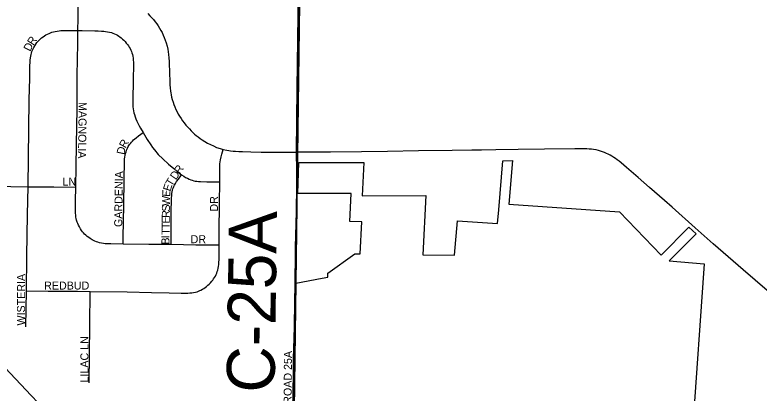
# Model space of a CAD drawing. Extents: x 0 to 680, y 0 to 440.
# Drawn here: x 483.77 to 499.3, y 268.76 to 276.66 of the extents above; entities that cross this region are included whole.
import ezdxf

# ---------------------------------------------------------------- set-up
doc = ezdxf.new("R2010")
doc.units = 0
for name, color, linetype in [('GM_X_City_Street', 7, 'Continuous'), ('GM_X_City_Street_Text', 7, 'Continuous'), ('GM_X_Corporation', 7, 'Continuous'), ('GM_X_County_Road', 7, 'Continuous'), ('GM_X_County_Road_Text', 7, 'Continuous'), ('GM_X_Interstate_Route', 7, 'Continuous'), ('GM_X_Section', 7, 'Continuous'), ('GM_X_Township_Subdivision', 7, 'Continuous'), ('GM_X_Township_Subdivision_Text', 7, 'Continuous')]:
    doc.layers.add(name, color=color, linetype=linetype)

msp = doc.modelspace()

# ---------------------------------------------------------------- linework, layer by layer
at = {"layer": 'GM_X_City_Street'}
msp.add_lwpolyline([(489.564, 267.937), (489.565, 267.993), (489.579, 268.809)], dxfattribs=at)
at = {"layer": 'GM_X_Corporation'}
msp.add_lwpolyline([(489.578, 268.503), (489.586, 269.459), (489.592, 269.713), (489.605, 270.077), (489.623, 270.72), (489.632, 271.054), (490.181, 271.16), (490.303, 271.181), (490.301, 271.265), (490.865, 271.669), (490.974, 271.667), (491.006, 272.34), (490.756, 272.347), (490.784, 272.931), (489.673, 272.926), (489.693, 273.575), (491.05, 273.58), (491.017, 272.88), (492.342, 272.885), (492.282, 271.649), (492.941, 271.638), (493.004, 272.359), (493.836, 272.304), (493.863, 272.585), (493.953, 273.614), (494.153, 273.616), (494.075, 272.707), (496.382, 272.544), (497.252, 271.643), (497.832, 272.227), (497.983, 272.09), (497.417, 271.525), (498.148, 271.46), (497.906, 267.992)], dxfattribs=at)
at = {"layer": 'GM_X_County_Road'}
for points in [[(489.648, 273.79), (489.648, 273.79), (489.658, 275.12), (489.681, 276.651), (489.681, 276.958)], [(486.546, 276.686), (486.588, 276.643), (486.629, 276.6), (486.663, 276.561), (486.698, 276.517), (486.732, 276.471), (486.76, 276.428), (486.789, 276.385), (486.816, 276.336), (486.841, 276.29), (486.866, 276.239), (486.889, 276.186), (486.908, 276.134), (486.929, 276.074), (486.946, 276.005), (486.961, 275.942), (486.969, 275.89), (486.977, 275.835), (486.985, 275.763), (486.99, 275.683), (486.999, 275.42), (487.002, 275.299), (487.007, 275.201), (487.013, 275.133), (487.019, 275.069), (487.025, 275.03), (487.031, 274.992), (487.041, 274.944), (487.053, 274.895), (487.07, 274.838), (487.087, 274.789), (487.108, 274.736), (487.13, 274.687), (487.156, 274.635), (487.181, 274.589), (487.208, 274.542), (487.239, 274.495), (487.271, 274.448), (487.303, 274.404), (487.34, 274.359), (487.374, 274.319), (487.411, 274.277), (487.447, 274.238), (487.482, 274.205), (487.52, 274.171), (487.556, 274.138), (487.592, 274.111), (487.636, 274.079), (487.68, 274.05), (487.733, 274.015), (487.791, 273.983), (487.851, 273.95), (487.912, 273.922), (487.979, 273.893), (488.054, 273.867), (488.118, 273.85)], [(488.118, 273.85), (488.19, 273.834), (488.232, 273.827), (488.272, 273.822), (488.324, 273.815), (488.376, 273.811), (488.444, 273.808), (488.519, 273.805), (488.694, 273.8), (488.909, 273.795), (489.163, 273.793), (489.648, 273.79)], [(497.323, 272.781), (497.009, 273.055), (496.771, 273.263), (496.528, 273.475), (496.415, 273.569), (496.375, 273.602), (496.336, 273.633), (496.3, 273.659), (496.262, 273.683), (496.226, 273.707), (496.188, 273.729), (496.149, 273.749), (496.111, 273.768), (496.073, 273.785), (496.032, 273.801), (495.99, 273.814), (495.945, 273.827), (495.897, 273.839), (495.844, 273.847), (495.802, 273.853), (495.752, 273.857), (495.699, 273.86), (495.639, 273.861), (495.453, 273.861), (494.819, 273.852), (494.27, 273.845), (493.801, 273.84), (493.505, 273.837)], [(491.004, 273.802), (490.354, 273.79), (489.648, 273.79)], [(489.651, 273.104), (489.651, 273.412), (489.648, 273.79)], [(493.303, 273.834), (492.892, 273.828), (492.192, 273.818), (491.546, 273.81), (491.004, 273.802)], [(493.505, 273.837), (493.303, 273.834)], [(489.616, 270.929), (489.616, 270.929), (489.627, 271.809), (489.643, 272.545), (489.651, 273.104)], [(497.48, 272.642), (497.323, 272.781)], [(499.544, 270.829), (499.46, 270.903), (498.964, 271.333), (498.337, 271.88), (497.959, 272.213), (497.48, 272.642)], [(489.609, 270.592), (489.609, 270.592), (489.613, 270.758), (489.616, 270.929)], [(489.599, 269.843), (489.604, 270.218), (489.609, 270.592)], [(489.579, 268.809), (489.589, 269.211), (489.599, 269.843)]]:
    msp.add_lwpolyline(points, dxfattribs=at)
at = {"layer": 'GM_X_Interstate_Route'}
msp.add_lwpolyline([(484.405, 268.404), (484.113, 268.711), (483.232, 269.636), (482.213, 270.707), (481.522, 271.432)], dxfattribs=at)
at = {"layer": 'GM_X_Section'}
msp.add_lwpolyline([(489.711, 276.904), (489.476, 259.394), (472.369, 259.414), (471.708, 259.407), (471.85, 277.333)], close=True, dxfattribs=at)
msp.add_lwpolyline([(507.727, 259.473), (489.476, 259.394), (489.711, 276.904)], dxfattribs=at)
at = {"layer": 'GM_X_Township_Subdivision'}
for points in [[(485.087, 276.331), (485.09, 276.584), (485.097, 277.092)], [(484.049, 273.072), (484.064, 274.277), (484.073, 274.888), (484.082, 275.34), (484.087, 275.601), (484.09, 275.666), (484.091, 275.713), (484.096, 275.762), (484.102, 275.797), (484.108, 275.829), (484.116, 275.861), (484.126, 275.894), (484.138, 275.923), (484.151, 275.954), (484.167, 275.982), (484.186, 276.015), (484.208, 276.047), (484.233, 276.081), (484.263, 276.115), (484.292, 276.145), (484.328, 276.178), (484.361, 276.202), (484.391, 276.223), (484.42, 276.241), (484.452, 276.258), (484.484, 276.274), (484.513, 276.286), (484.543, 276.297), (484.576, 276.307), (484.614, 276.316), (484.655, 276.322), (484.695, 276.327), (484.733, 276.331), (484.771, 276.332), (485.087, 276.331)], [(485.042, 273.063), (485.049, 273.495), (485.056, 273.943), (485.069, 274.702), (485.074, 275.391), (485.083, 276.064), (485.087, 276.331)], [(485.087, 276.331), (485.176, 276.331), (485.437, 276.326), (485.512, 276.324), (485.581, 276.322), (485.626, 276.319), (485.665, 276.315), (485.705, 276.309), (485.745, 276.3), (485.784, 276.289), (485.817, 276.277), (485.852, 276.263), (485.882, 276.249), (485.91, 276.235), (485.937, 276.218), (485.963, 276.2), (485.987, 276.18), (486.015, 276.156), (486.044, 276.129), (486.071, 276.101), (486.096, 276.072), (486.12, 276.043), (486.142, 276.011), (486.158, 275.985), (486.176, 275.955), (486.19, 275.925), (486.203, 275.895), (486.214, 275.865), (486.224, 275.831), (486.231, 275.796), (486.237, 275.757), (486.242, 275.714), (486.244, 275.67), (486.246, 275.626), (486.246, 275.575), (486.242, 275.353), (486.23, 274.827), (486.231, 274.78), (486.233, 274.736), (486.237, 274.699), (486.244, 274.658), (486.254, 274.616), (486.266, 274.576), (486.281, 274.533), (486.297, 274.488), (486.317, 274.441), (486.344, 274.385), (486.367, 274.34), (486.391, 274.297), (486.445, 274.2)], [(486.031, 271.873), (486.033, 272.018), (486.044, 272.682), (486.05, 273.218), (486.057, 273.613), (486.059, 273.65), (486.064, 273.689), (486.071, 273.728), (486.08, 273.764), (486.091, 273.802), (486.102, 273.832), (486.114, 273.862), (486.126, 273.887), (486.138, 273.909), (486.152, 273.931), (486.165, 273.951), (486.183, 273.975), (486.201, 273.999), (486.222, 274.022), (486.247, 274.047), (486.275, 274.074), (486.3, 274.095), (486.353, 274.133), (486.445, 274.2)], [(486.445, 274.2), (486.534, 274.056), (486.608, 273.944), (486.645, 273.89), (486.684, 273.839), (486.763, 273.746), (486.855, 273.652), (486.975, 273.54), (487.084, 273.449), (487.164, 273.384), (487.246, 273.321)], [(488.045, 273.171), (488.046, 273.489), (488.049, 273.546), (488.055, 273.589), (488.061, 273.634), (488.073, 273.694), (488.086, 273.752), (488.118, 273.85)], [(487.029, 271.861), (487.03, 271.958), (487.032, 272.3), (487.035, 272.637), (487.036, 272.711), (487.037, 272.77), (487.04, 272.837), (487.043, 272.889), (487.047, 272.927), (487.053, 272.965), (487.06, 272.999), (487.069, 273.028), (487.079, 273.053), (487.089, 273.079), (487.103, 273.106), (487.12, 273.137), (487.146, 273.179), (487.182, 273.229), (487.246, 273.321)], [(487.246, 273.321), (487.293, 273.29), (487.334, 273.266), (487.369, 273.247), (487.405, 273.231), (487.44, 273.217), (487.471, 273.206), (487.502, 273.197), (487.535, 273.19), (487.567, 273.185), (487.603, 273.18), (487.643, 273.178), (487.776, 273.174), (488.045, 273.171)], [(483.557, 273.081), (483.686, 273.078), (484.049, 273.072)], [(484.016, 270.897), (484.022, 271.618), (484.038, 272.493), (484.049, 273.072)], [(484.049, 273.072), (484.585, 273.067), (485.042, 273.063)], [(486.031, 271.873), (485.773, 271.876), (485.712, 271.877), (485.653, 271.881), (485.617, 271.885), (485.577, 271.891), (485.538, 271.9), (485.502, 271.911), (485.472, 271.921), (485.441, 271.934), (485.411, 271.949), (485.383, 271.964), (485.345, 271.988), (485.313, 272.009), (485.281, 272.033), (485.249, 272.06), (485.225, 272.083), (485.203, 272.106), (485.182, 272.132), (485.162, 272.158), (485.14, 272.192), (485.117, 272.233), (485.1, 272.266), (485.084, 272.302), (485.072, 272.334), (485.059, 272.374), (485.05, 272.406), (485.044, 272.438), (485.04, 272.475), (485.037, 272.518), (485.036, 272.569), (485.034, 272.668), (485.037, 272.775), (485.042, 273.063)], [(488.033, 271.847), (488.036, 272.121), (488.042, 272.728), (488.045, 273.171)], [(485.342, 270.885), (486.117, 270.873), (486.622, 270.861), (486.992, 270.854), (487.239, 270.849), (487.327, 270.848), (487.379, 270.849), (487.423, 270.852), (487.46, 270.856), (487.501, 270.862), (487.538, 270.87), (487.572, 270.879), (487.601, 270.89), (487.627, 270.901), (487.653, 270.913), (487.682, 270.929), (487.711, 270.946), (487.739, 270.965), (487.766, 270.986), (487.798, 271.012), (487.824, 271.037), (487.85, 271.064), (487.878, 271.095), (487.898, 271.119), (487.918, 271.148), (487.935, 271.175), (487.953, 271.206), (487.968, 271.235), (487.982, 271.267), (487.993, 271.298), (488.003, 271.331), (488.012, 271.368), (488.019, 271.408), (488.024, 271.449), (488.028, 271.497), (488.03, 271.547), (488.03, 271.607), (488.033, 271.847)], [(487.029, 271.861), (486.564, 271.866), (486.031, 271.873)], [(488.033, 271.847), (487.547, 271.853), (487.029, 271.861)], [(484.002, 270.145), (484.008, 270.521), (484.016, 270.897)], [(484.016, 270.897), (484.465, 270.893), (485.075, 270.888), (485.342, 270.885)], [(485.318, 268.972), (485.325, 269.568), (485.333, 270.187), (485.342, 270.885)]]:
    msp.add_lwpolyline(points, dxfattribs=at)

# ---------------------------------------------------------------- texts
at = {"layer": 'GM_X_City_Street_Text'}
msp.add_text('S COUNTY ROAD 25A', height=0.16689, rotation=89.5866, dxfattribs=at).set_placement((489.535, 267.322))
at = {"layer": 'GM_X_County_Road_Text'}
msp.add_text('C-25A', height=1.0014, rotation=89.2439, dxfattribs=at).set_placement((489.189, 268.766))
at = {"layer": 'GM_X_Township_Subdivision_Text'}
for s, height, rotation, p in [('R', 0.167, 57.1991, (484.156, 276.01)), ('D', 0.167, 62.389, (484.089, 275.883)), ('MAGNOLIA', 0.1669, 269.2466, (485.104, 274.841)), ('R', 0.167, 61.0775, (486.08, 273.863)), ('D', 0.167, 77.7343, (486.053, 273.731)), ('GARDENIA', 0.1669, 89.2148, (486.01, 272.228)), ('D', 0.167, 54.7215, (487.129, 273.201)), ('R', 0.167, 55.6246, (487.215, 273.323)), ('LN', 0.1669, 0, (484.764, 273.096)), ('T', 0.167, 59.3502, (487.046, 273.066)), ('E', 0.167, 72.3771, (487.015, 272.963)), ('E', 0.167, 86.3095, (487.009, 272.856)), ('W', 0.167, 89.1325, (487.007, 272.668)), ('DR', 0.1669, 90, (488.008, 272.551)), ('S', 0.167, 89.1257, (487.005, 272.55)), ('R', 0.167, 89.139, (487.003, 272.418)), ('T', 0.167, 89.1412, (486.999, 272.183)), ('E', 0.167, 89.1257, (487.001, 272.3)), ('T', 0.167, 89.1257, (486.998, 272.065)), ('B', 0.167, 89.15, (486.994, 271.86)), ('I', 0.167, 89.126, (486.996, 271.992)), ('DR', 0.1669, 0, (487.437, 271.892)), ('WISTERIA', 0.1669, 90, (483.984, 270.172)), ('REDBUD', 0.1669, 0, (484.382, 270.923)), ('LILAC LN', 0.1669, 90, (485.305, 268.982))]:
    msp.add_text(s, height=height, rotation=rotation, dxfattribs=at).set_placement(p)

doc.saveas('drawing.dxf')
